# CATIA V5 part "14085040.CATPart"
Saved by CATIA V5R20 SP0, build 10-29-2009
Part number: 14085040
Definition: NONE
Nomenclature: 14085040
Source: Unknown
Description: 14085040
Bounding box of the stored display mesh (mm): x -20 to 80, y -56.5 to 46.401, z -46.6 to 46.6
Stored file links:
  C:\Users\Utente\Desktop\IO LAVORO\3D X SITO CF\X SITO\PLASTICA\RF2\14085040.CATPart
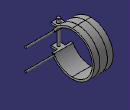
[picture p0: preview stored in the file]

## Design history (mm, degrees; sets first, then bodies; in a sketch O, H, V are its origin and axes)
Body1 "14085040" (main body)
  Solid1: solid without history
